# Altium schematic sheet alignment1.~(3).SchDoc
size A4
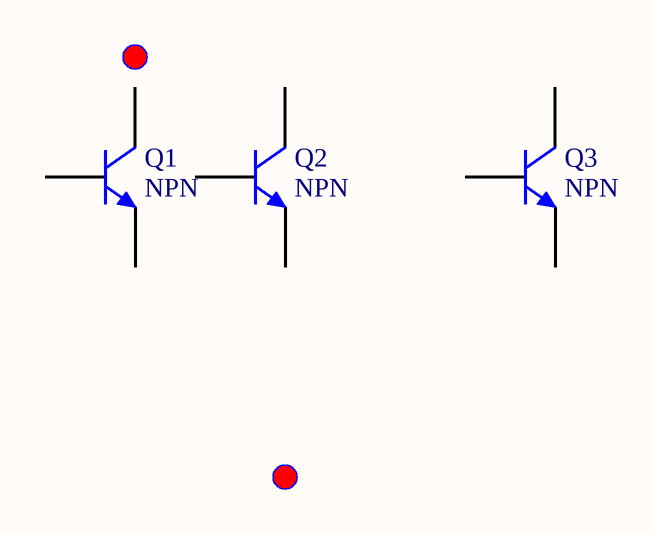
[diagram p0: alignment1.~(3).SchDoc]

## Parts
Q1  NPN  [BCY-W3]
Q2  NPN  [BCY-W3]
Q3  NPN  [BCY-W3]

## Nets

Not connected (* = marked no-connect by the designer): Q1 1(C) 2(B) 3(E); Q2 1(C) 2(B) 3(E); Q3 1(C) 2(B) 3(E)

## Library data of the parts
Q1-Q3 = NPN: NPN Bipolar Transistor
